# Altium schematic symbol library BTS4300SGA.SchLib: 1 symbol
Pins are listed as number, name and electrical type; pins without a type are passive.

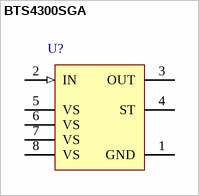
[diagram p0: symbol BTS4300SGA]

## BTS4300SGA
designator U?
Smart Power High-Side-Switch, 1 Channel, 1.1 A Load Current, -40 to 150 degC, PG-DSO-8-24, Reel, Green; Manufacturer: Infineon; PartNumber: BTS4300SGA; Channels: 1; Green: TRUE; Group: Automotive Qualified; Load Current (typ): 1.1 A; Packing: Tube; Ptot (max): 1.5 W; Recommended Operating Voltage Max.: 34 V; Recommended Operating Voltage Min.: 5 V; RON @ 25degreesC: 300 mOhm; RON(max) @ 150degreesC: 600 mOhm; toff (max): 170 us; ton (max): 140 us
footprint INF-PG-DSO-8-24_N (SOP, 8-Leads, Body 4.9x3.9mm, Pitch 1.27mm, IPC Medium Density)
footprint INF-PG-DSO-8-24_L (SOP, 8-Leads, Body 4.9x3.9mm, Pitch 1.27mm, IPC High Density)
footprint INF-PG-DSO-8-24_M (SOP, 8-Leads, Body 4.9x3.9mm, Pitch 1.27mm, IPC Low Density)
pins: 1 GND (power) "Ground; Ground connection", 2 IN (in) "Input channel; Input signal. Activate the channel in case of logic high level", 3 OUT (power) "Output; Protected High side power output channel", 4 ST (oc) "Diagnostic feedback; of channel. Open drain.", 5 VS (power) "Battery voltage; Design the wiring for the simultaneous max. short circuit current and also for low thermal resistance", 6 VS (power) "Battery voltage; Design the wiring for the simultaneous max. short circuit current and also for low thermal resistance", 7 VS (power) "Battery voltage; Design the wiring for the simultaneous max. short circuit current and also for low thermal resistance", 8 VS (power) "Battery voltage; Design the wiring for the simultaneous max. short circuit current and also for low thermal resistance"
